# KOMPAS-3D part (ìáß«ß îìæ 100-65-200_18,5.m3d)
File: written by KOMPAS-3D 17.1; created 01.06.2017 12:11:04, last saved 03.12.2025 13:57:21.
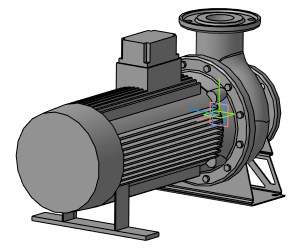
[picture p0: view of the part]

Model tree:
1. Операция без истории:7

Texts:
  ООО АДЛ ГРУПП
